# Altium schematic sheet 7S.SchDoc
size 431 x 279 mm; Date: Not shown in title block; ApprovedBy: Not shown in title block; CheckedBy: Not shown in title block; Author: Not shown in title block; CompanyName: Not shown in title block; Engineer: Not shown in title block; Organization: Not shown in title block; Address1: Not shown in title block; Address2: Not shown in title block; Address3: Not shown in title block; Address4: Not shown in title block; DocumentNumber: 3; Revision: Use project parameter SCH_Rev; SheetNumber: 3; SheetTotal: 5; PageSetup: Record=PageOptions¦CenterHorizontal=True¦CenterVertical=True¦PrintScale=0.64¦XCorrection=1.00¦YCorrection=1.00¦PrintKind=0¦BorderSize=5000000¦LeftOffset=0¦BottomOffset=0¦Orientation=2¦PaperLength=1000¦PaperWidth=1000¦Scale=100¦PaperSource=15¦PrintQuality=600¦MediaType=1¦DitherType=10¦PrintScaleMode=1¦PaperKind=Letter
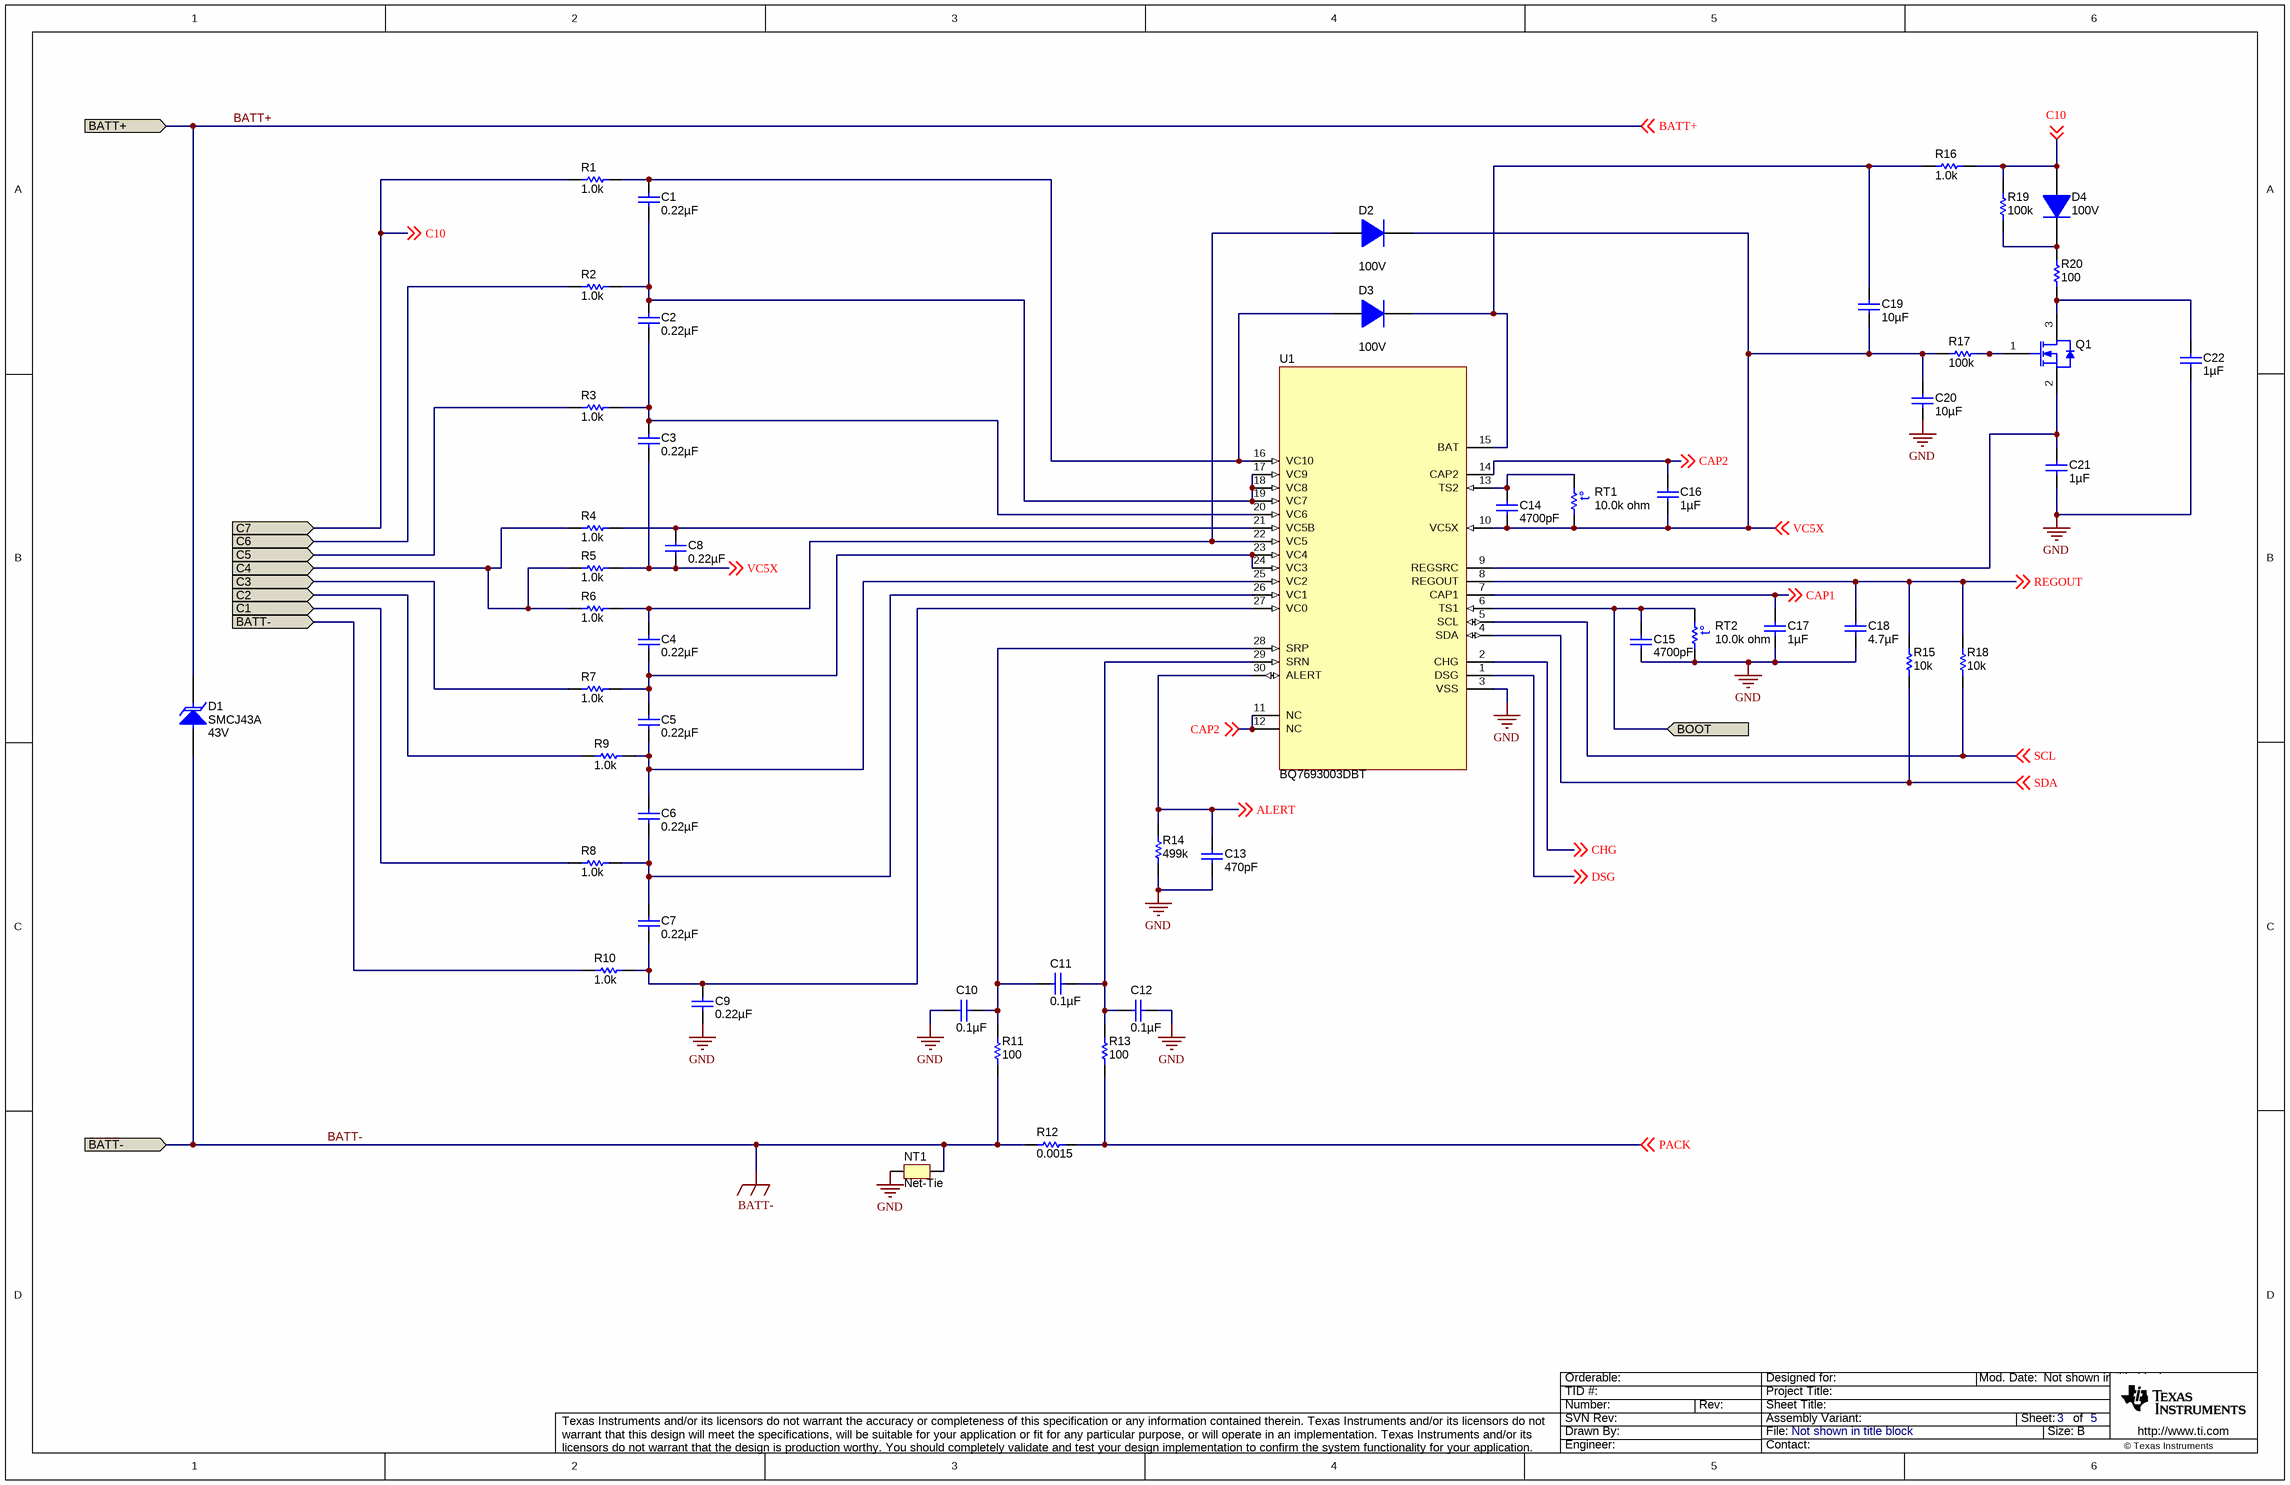
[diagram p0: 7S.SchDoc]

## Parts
C1  ValueDisplayed: 0.22µF  [0603_095]  (hidden comment: 885012206048)
C2  ValueDisplayed: 0.22µF  [0603_095]  (hidden comment: 885012206048)
C3  ValueDisplayed: 0.22µF  [0603_095]  (hidden comment: 885012206048)
C4  ValueDisplayed: 0.22µF  [0603_095]  (hidden comment: 885012206048)
C5  ValueDisplayed: 0.22µF  [0603_095]  (hidden comment: 885012206048)
C6  ValueDisplayed: 0.22µF  [0603_095]  (hidden comment: 885012206048)
C7  ValueDisplayed: 0.22µF  [0603_095]  (hidden comment: 885012206048)
C8  ValueDisplayed: 0.22µF  [0603_095]  (hidden comment: 885012206048)
C9  ValueDisplayed: 0.22µF  [0603_095]  (hidden comment: 885012206048)
C10  ValueDisplayed: 0.1µF  [0603_095]  (hidden comment: 885012206095)
C11  ValueDisplayed: 0.1µF  [0603_095]  (hidden comment: 885012206095)
C12  ValueDisplayed: 0.1µF  [0603_095]  (hidden comment: 885012206095)
C13  ValueDisplayed: 470pF  [0603_095]  (hidden comment: 885012206081)
C14  ValueDisplayed: 4700pF  [0603_095]  (hidden comment: 885012206087)
C15  ValueDisplayed: 4700pF  [0603_095]  (hidden comment: 885012206087)
C16  ValueDisplayed: 1µF  [0603_095]  (hidden comment: 885012206052)
C17  ValueDisplayed: 1µF  [0603_095]  (hidden comment: 885012206052)
C18  ValueDisplayed: 4.7µF  [0805_145]  (hidden comment: 885012207025)
C19  ValueDisplayed: 10µF  [1210]  (hidden comment: GRM32ER7YA106KA12L)
C20  ValueDisplayed: 10µF  [1210]  (hidden comment: GRM32ER7YA106KA12L)
C21  ValueDisplayed: 1µF  [0805]  (hidden comment: GRM21BR71H105KA12L)
C22  ValueDisplayed: 1µF  [0805_HV]  (hidden comment: GRM21BR71H105KA12L)
D1  SMCJ43A  value 43V  [SMC_265]
D2  value 100V  [SOD-123]  (hidden comment: 1N4148W-7-F)
D3  value 100V  [SOD-123]  (hidden comment: 1N4148W-7-F)
D4  value 100V  [SOD-123]  (hidden comment: 1N4148W-7-F)
NT1  Net-Tie  [Net-Tie_10mil]  (net tie, no BOM)
Q1  2N7002ET1G  [SOT-23]  (value not drawn)
R1  ValueDisplayed: 1.0k  [0603]  (hidden comment: CRCW06031K00JNEA)
R2  ValueDisplayed: 1.0k  [0603]  (hidden comment: CRCW06031K00JNEA)
R3  ValueDisplayed: 1.0k  [0603]  (hidden comment: CRCW06031K00JNEA)
R4  ValueDisplayed: 1.0k  [0603]  (hidden comment: CRCW06031K00JNEA)
R5  ValueDisplayed: 1.0k  [0603]  (hidden comment: CRCW06031K00JNEA)
R6  ValueDisplayed: 1.0k  [0603]  (hidden comment: CRCW06031K00JNEA)
R7  ValueDisplayed: 1.0k  [0603]  (hidden comment: CRCW06031K00JNEA)
R8  ValueDisplayed: 1.0k  [0603]  (hidden comment: CRCW06031K00JNEA)
R9  ValueDisplayed: 1.0k  [0603]  (hidden comment: CRCW06031K00JNEA)
R10  ValueDisplayed: 1.0k  [0603]  (hidden comment: CRCW06031K00JNEA)
R11  value 100  [0805_HV]  (hidden comment: CRCW0805100RFKEA)
R12  ValueDisplayed: 0.0015  [ULRB22512_085]  (hidden comment: ULRB22512R0015FLFSLT)
R13  value 100  [0805_HV]  (hidden comment: CRCW0805100RFKEA)
R14  ValueDisplayed: 499k  [0603]  (hidden comment: CRCW0603499KFKEA)
R15  ValueDisplayed: 10k  [0603]  (hidden comment: CRCW060310K0JNEA)
R16  ValueDisplayed: 1.0k  [0603]  (hidden comment: CRCW06031K00JNEA)
R17  value 100k  [0805_HV]  (hidden comment: CRCW0805100KFKEA)
R18  ValueDisplayed: 10k  [0603]  (hidden comment: CRCW060310K0JNEA)
R19  value 100k  [0805_HV]  (hidden comment: CRCW0805100KFKEA)
R20  value 100  [0805_HV]  (hidden comment: CRCW0805100RFKEA)
RT1  value 10.0k ohm  [Thermistor_103AT-2]  (hidden comment: 103AT-2)
RT2  value 10.0k ohm  [Thermistor_103AT-2]  (hidden comment: 103AT-2)
U1  BQ7693003DBT  [DBT0030A_N]

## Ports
BATT+, BATT-, BOOT, C1, C2, C3, C4, C5, C6, C7

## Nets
BATT-: D1.2(A) NT1.2 R10.1 R11.1 R12.1 ; port BATT-
GND: C9.2 C10.2 C12.1 C13.2 C15.2 C17.2 C18.2 C20.2 C21.2 C22.2 NT1.1 R14.1 RT2.1 U1.3(VSS)
ALERT: C13.1 R14.2 U1.30(ALERT) ; off-sheet ALERT
BATT+: D1.1(K) ; off-sheet BATT+, port BATT+
BOOT: C15.1 RT2.2 U1.6(TS1) ; port BOOT
C1: R8.1 ; port C1
C2: R9.1 ; port C2
C3: R7.1 ; port C3
C4: R4.1 R5.1 R6.1 ; port C4
C5: R3.1 ; port C5
C6: R2.1 ; port C6
C10: D4.2(A) R1.1 R16.2 R19.1 ; off-sheet C10, port C7
CAP1: C17.1 U1.7(CAP1) ; off-sheet CAP1
CAP2: C16.1 U1.11(NC) U1.12(NC) U1.14(CAP2) ; off-sheet CAP2
CHG: U1.2(CHG) ; off-sheet CHG
DSG: U1.1(DSG) ; off-sheet DSG
PACK: R12.2 R13.1 ; off-sheet PACK
REGOUT: C18.1 R15.2 R18.1 U1.8(REGOUT) ; off-sheet REGOUT
SCL: R18.2 U1.5(SCL) ; off-sheet SCL
SDA: R15.1 U1.4(SDA) ; off-sheet SDA
VC5X: C3.2 C8.2 C14.2 C16.2 C19.2 C20.1 D2.1(K) R5.2 R17.1 RT1.1 U1.10(VC5X) ; off-sheet VC5X
NetC1_1: C1.1 D3.2(A) R1.2 U1.16(VC10)
NetC1_2: C1.2 C2.1 R2.2 U1.17(VC9) U1.18(VC8) U1.19(VC7)
NetC2_2: C2.2 C3.1 R3.2 U1.20(VC6)
NetC4_1: C4.1 D2.2(A) R6.2 U1.22(VC5)
NetC4_2: C4.2 C5.1 R7.2 U1.23(VC4) U1.24(VC3)
NetC5_2: C5.2 C6.1 R9.2 U1.25(VC2)
NetC6_2: C6.2 C7.1 R8.2 U1.26(VC1)
NetC7_2: C7.2 C9.1 R10.2 U1.27(VC0)
NetC8_1: C8.1 R4.2 U1.21(VC5B)
NetC10_1: C10.1 C11.2 R11.2 U1.28(SRP)
NetC11_1: C11.1 C12.2 R13.2 U1.29(SRN)
NetC14_1: C14.1 RT1.2 U1.13(TS2)
NetC19_1: C19.1 D3.1(K) R16.1 U1.15(BAT)
NetC21_1: C21.1 Q1.2(S) U1.9(REGSRC)
NetC22_1: C22.1 Q1.3(D) R20.2
NetD4_1: D4.1(K) R19.2 R20.1
NetQ1_1: Q1.1(G) R17.2

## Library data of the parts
C1-C9 = 885012206048: CAP, CERM, 0.22 µF, 16 V, +/- 10%, X7R, 0603_095; Manufacturer: Wurth Elektronik; Polarized: N; CompType: Capacitor; Value: 0.22uF; U/M: EA; Cap_F: 0.00000022; Tolerance_%: 10; Value1: Unknown; VDC_V: 16; Value2: 16V; TaMin_C: -55; TaMax_C: 125; Cap_Case: 0603
C10-C12 = 885012206095: CAP, CERM, 0.1 µF, 50 V, +/- 10%, X7R, 0603_095; Manufacturer: Wurth Elektronik; Polarized: N; CompType: Capacitor; Value: 0.1uF; U/M: EA; Cap_F: 0.0000001; Tolerance_%: 10; Value1: Unknown; VDC_V: 50; Value2: 50V; TaMin_C: -55; TaMax_C: 125; Cap_Case: 0603
C13 = 885012206081: CAP, CERM, 470 pF, 50 V, +/- 10%, X7R, 0603_095; Manufacturer: Wurth Elektronik; Polarized: N; CompType: Capacitor; Value: 470pF; U/M: EA; Cap_F: 0.00000000047; Tolerance_%: 10; Value1: Unknown; VDC_V: 50; Value2: 50V; TaMin_C: -55; TaMax_C: 125; Cap_Case: 0603
C14 C15 = 885012206087: CAP, CERM, 4700 pF, 50 V, +/- 10%, X7R, 0603_095; Manufacturer: Wurth Elektronik; Polarized: N; CompType: Capacitor; Value: 4700pF; U/M: EA; Cap_F: 0.0000000047; Tolerance_%: 10; Value1: Unknown; VDC_V: 50; Value2: 50V; TaMin_C: -55; TaMax_C: 125; Cap_Case: 0603
C16 C17 = 885012206052: CAP, CERM, 1 µF, 16 V, +/- 10%, X7R, 0603_095; Manufacturer: Wurth Elektronik; Polarized: N; CompType: Capacitor; Value: 1uF; U/M: EA; Cap_F: 0.000001; Tolerance_%: 10; Value1: Unknown; VDC_V: 16; Value2: 16V; TaMin_C: -55; TaMax_C: 125; Cap_Case: 0603
C18 = 885012207025: CAP, CERM, 4.7 µF, 10 V, +/- 10%, X7R, 0805; Manufacturer: Wurth Elektronik; Polarized: N; CompType: Capacitor; Value: 4.7uF; U/M: EA; Cap_F: 0.0000047; Tolerance_%: 10; Value1: Unknown; Value2: 10V; TaMin_C: -55; TaMax_C: 125; Cap_Case: 0805
C19 C20 = GRM32ER7YA106KA12L: CAP, CERM, 10uF, 35V, +/-10%, X7R, 1210; Manufacturer: MuRata; Polarized: N; CompType: Capacitor; U/M: EA; Cap_F: 0.00001; Tolerance_%: 10; Value1: Unknown; VDC_V: 35; TaMin_C: -55; TaMax_C: 125
C21 = GRM21BR71H105KA12L: CAP, CERM, 1 µF, 50 V, +/- 10%, X7R, 0805; Manufacturer: MuRata; Polarized: N; CompType: Capacitor; Value: 1uF; U/M: EA; Cap_F: 0.000001; Tolerance_%: 10; Value1: Unknown; VDC_V: 50; Value2: 50V; TaMin_C: -55; TaMax_C: 125
C22 = GRM21BR71H105KA12L: CAP, CERM, 1 µF, 50 V, +/- 10%, X7R, 0805; Manufacturer: MuRata; Polarized: N; CompType: Capacitor; Value: 1uF; U/M: EA; Cap_F: 0.000001; Tolerance_%: 10; Value1: Unknown; VDC_V: 50; Value2: 50V; TaMin_C: -55; TaMax_C: 125; Cap_Case: 0805
D1 = SMCJ43A: Diode, TVS, Uni, 43 V, 69.4 Vc, SMC; Manufacturer: Fairchild Semiconductor; U/M: EA; Vr_V: 43; Value1: W; SizeAreaWB_mm2: 78.5757; SizeArea_mm2: 46.8857; SizeX_mm: 7.94; SizeY_mm: 5.905; SizeZ_mm: 2.62; AEC Category: Q101
D2 D3 = 1N4148W-7-F: Diode, Ultrafast, 100V, 0.15A, SOD-123; Manufacturer: Diodes Inc.; U/M: EA; Vf_V: 1.25; Value2: 1.25V; Io_A: 0.15; Vr_V: 100; TJmax_C: 150
D4 = 1N4148W-7-F: Diode, Ultrafast, 100V, 0.15A, SOD-123; Manufacturer: Diodes Inc.; U/M: EA; Vf_V: 1.25; Io_A: 0.15; Vr_V: 100; Value2: 1.25V; TJmax_C: 150
NT1 = Net-Tie: Single point connection between nets.; SymbolCreator: codlsc
Q1 = 2N7002ET1G: MOSFET, N-CH, 60 V, 0.26 A, SOT-23; Manufacturer: ON Semiconductor; Alternate Manufacturer: None; U/M: EA; ChType: N; Value: 60V; VdsMax_V: 60; Value1: 3 ohm; Rdson45_ohm: 3; Value2: 0.81 nC; QgTyp_nC: 0.81; Vgs_V: 20; IdsMax_A: 0.26
R1-R10 R16 = CRCW06031K00JNEA: RES, 1.0 k, 5%, 0.1 W, 0603; Manufacturer: Vishay-Dale; CompType: Resistor; Value: 1.0k; Res_ohm: 1000; Value_Code: 1k00; Tolerance_%: 5; Power_W: 0.1; Value2: 0.1W; VDC_V: 75; TempCo: 200 ppm/C; EIA_Code: E24; U/M: EA
R11 R13 R20 = CRCW0805100RFKEA: RES, 100 ohm, 1%, 0.125W, 0805; Manufacturer: Vishay-Dale; CompType: Resistor; Value_Code: 100R; Tolerance_%: 1; Power_W: 0.125; VDC_V: 150; TempCo: 100 ppm/C; EIA_Code: E96; U/M: EA
R12 = ULRB22512R0015FLFSLT: RES, 0.0015, 1%, 2 W, AEC-Q200 Grade 0, 2512; Manufacturer: TT Electronics/IRC; CompType: Resistor; Value: 0.0015; Value_Code: 1L500; Tolerance_%: 1; Power_W: 2; Value2: 2W; TempCo: 50 ppm/C; U/M: EA; AEC Category: Q200; AEC Qualified: Y; AEC Grade: 0
R14 = CRCW0603499KFKEA: RES, 499 k, 1%, 0.1 W, 0603; Manufacturer: Vishay-Dale; CompType: Resistor; Value: 499k; Res_ohm: 499000; Tolerance_%: 1; Power_W: 0.1; Value2: 0.1W; VDC_V: 75; TempCo: 100 ppm/C; EIA_Code: E96; U/M: EA
R15 R18 = CRCW060310K0JNEA: RES, 10 k, 5%, 0.1 W, 0603; Manufacturer: Vishay-Dale; CompType: Resistor; Value: 10k; Res_ohm: 10000; Value_Code: 10k0; Tolerance_%: 5; Power_W: 0.1; Value2: 0.1W; VDC_V: 75; TempCo: 200 ppm/C; EIA_Code: E24; U/M: EA
R17 R19 = CRCW0805100KFKEA: RES, 100k ohm, 1%, 0.125W, 0805; Manufacturer: Vishay-Dale; CompType: Resistor; Res_ohm: 100000; Tolerance_%: 1; Power_W: 0.125; VDC_V: 150; TempCo: 100 ppm/C; EIA_Code: E96; U/M: EA
RT1 RT2 = 103at-2: Thermistor NTC, 10.0k ohm, 1%, Disc, 5x8.4 mm; Manufacturer: SEMITEC Corporation; Tolerance_%: 1; Power_W: 0.01; TaMin_C: -50; TaMax_C: 110; U/M: EA
U1 = BQ7693003DBT: Battery Monitor for Lithium-Ion and Phosphate Battery Packs, DBT0030A; Manufacturer: Texas Instruments; SymbolCreator: a0799628; CompType: IC; U/M: EA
